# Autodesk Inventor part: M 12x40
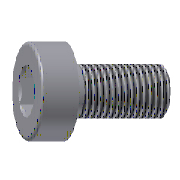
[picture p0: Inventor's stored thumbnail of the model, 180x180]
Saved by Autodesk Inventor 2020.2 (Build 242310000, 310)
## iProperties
Manager: www.cadconsulting.pl
Company: Fabian Stasiak CAD Consulting
Created: 2014-02
Part Number: M 12x40
Material: Stal, miękka
Description: Socket Head Cap Screw DIN 912 - 12.9
Document SubType Name: Modeling
Designer: F.Stasiak
Standard Revision: 1
Manufacturer: DME
Language: pl-PL
Size Designation: 12x40
Categories: <MemberInstance><Categories><Category DisplayName="Forma wtryskowa" InternalName="349578f2-f4d4-4954-8c09-8e99297a61c0" Mnemonic="MOLD"><Category DisplayName="C
Mass: 0.133121 g
Surface Area: 2.01441 cm^2
Volume: 0.133121 cm^3
Density: 7.85 g/cm^3
Appearance: Częściowo polerowana
Catalog Web Link: www.expertbooks.pl
IsCustomPart: 0
Author: F.Stasiak
Subject: Zbiór ćwiczeń. Autodesk Inventor 2020. Kurs Professional
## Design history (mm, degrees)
sketch "Sketch1"
  geometry: L1 (0, -50.4)-(0, 22.4) reference; L2 (5.774, 12)-(9, 12); L3 (9, 12)-(9, 0); L4 (9, 0)-(6, 0); L5 (6, 0)-(6, -40); L6 (6, -40)-(0, -40); L7 (0, 2.996)-(0, -40); L8 (0, 2.996)-(5, 6); L9 (5, 6)-(5, 11.226); L10 (5, 11.226)-(5.774, 12); 1 further point
  constraints: 18 end point, 4 vertical, 3 horizontal, 2 point on line
  dimensions: "d0" = 18 diameter of L3 L1 (= dk); "d1" = 12 distance between parallel lines of L4 L2 (= k); "d2" = 12 diameter of L5 L1 (= d); "d3" = 40 distance between parallel lines of L6 L4 (= L); "d4" = 59 deg angle of L1 L8; "d5" = 45 deg angle of L1 L10; "d6" = 10 diameter of L9 L1 (= sw); "d7" = 11.54701 diameter of L2.start L1 (= 1.1547 x sw); "d8" = 6 distance from line of L8.end L2 (= t)
revolve "Revolution1" sketch "Sketch1" stored, may be unused: angle "d44" = 90 deg
sketch "Sketch2"
  geometry: L1 (0, 5.774)-(5, 2.887); L2 (5, 2.887)-(5, -2.887); L3 (5, -2.887)-(0, -5.774); L4 (0, -5.774)-(-5, -2.887); L5 (-5, -2.887)-(-5, 2.887); L6 (-5, 2.887)-(0, 5.774); 3 further points
  constraints: 12 end point, 2 vertical alignment, 1 coincident, 14 other
extrude "Extrusion1" cut sketch "Sketch2" taper "d9" = 0 deg; stored distance "d45" = 10
thread "Thread1" dims "d10" = 28 (= b), "d11" = 0
chamfer "Chamfer1" distance "d12" = 0.875 (= 0.5 x P); stored, may be unused: second distance "d50" = 2, angle "d51" = 45 deg
fillet "Fillet1" dims "d13" = 0.875 (= 0.5 x P)
body "Solid1"
other parameters: "d" = 12 [user parameter; used in 1 equation term], "L" = 40 [user parameter; used in 1 equation term], "dk" = 18 [user parameter; used in 1 equation term], "b" = 28 [user parameter; used in 1 equation term], "k" = 12 [user parameter; used in 1 equation term], "sw" = 10 [user parameter; used in 2 equation terms], "t" = 6 [user parameter; used in 1 equation term], "P" = 1.75 [user parameter; used in 2 equation terms], "d14" = 0, "d15" = 0, "d55" = 0
